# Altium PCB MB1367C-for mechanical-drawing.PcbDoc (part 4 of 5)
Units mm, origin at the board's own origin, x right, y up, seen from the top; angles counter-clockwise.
Board outline 70 x 82.5 mm, 4 copper layers (Top Layer, Signal Layer 1, Signal Layer 2, Bottom Layer), stack 1.614 mm thick; 191 components, 143 nets, 808 pads, 920 vias.
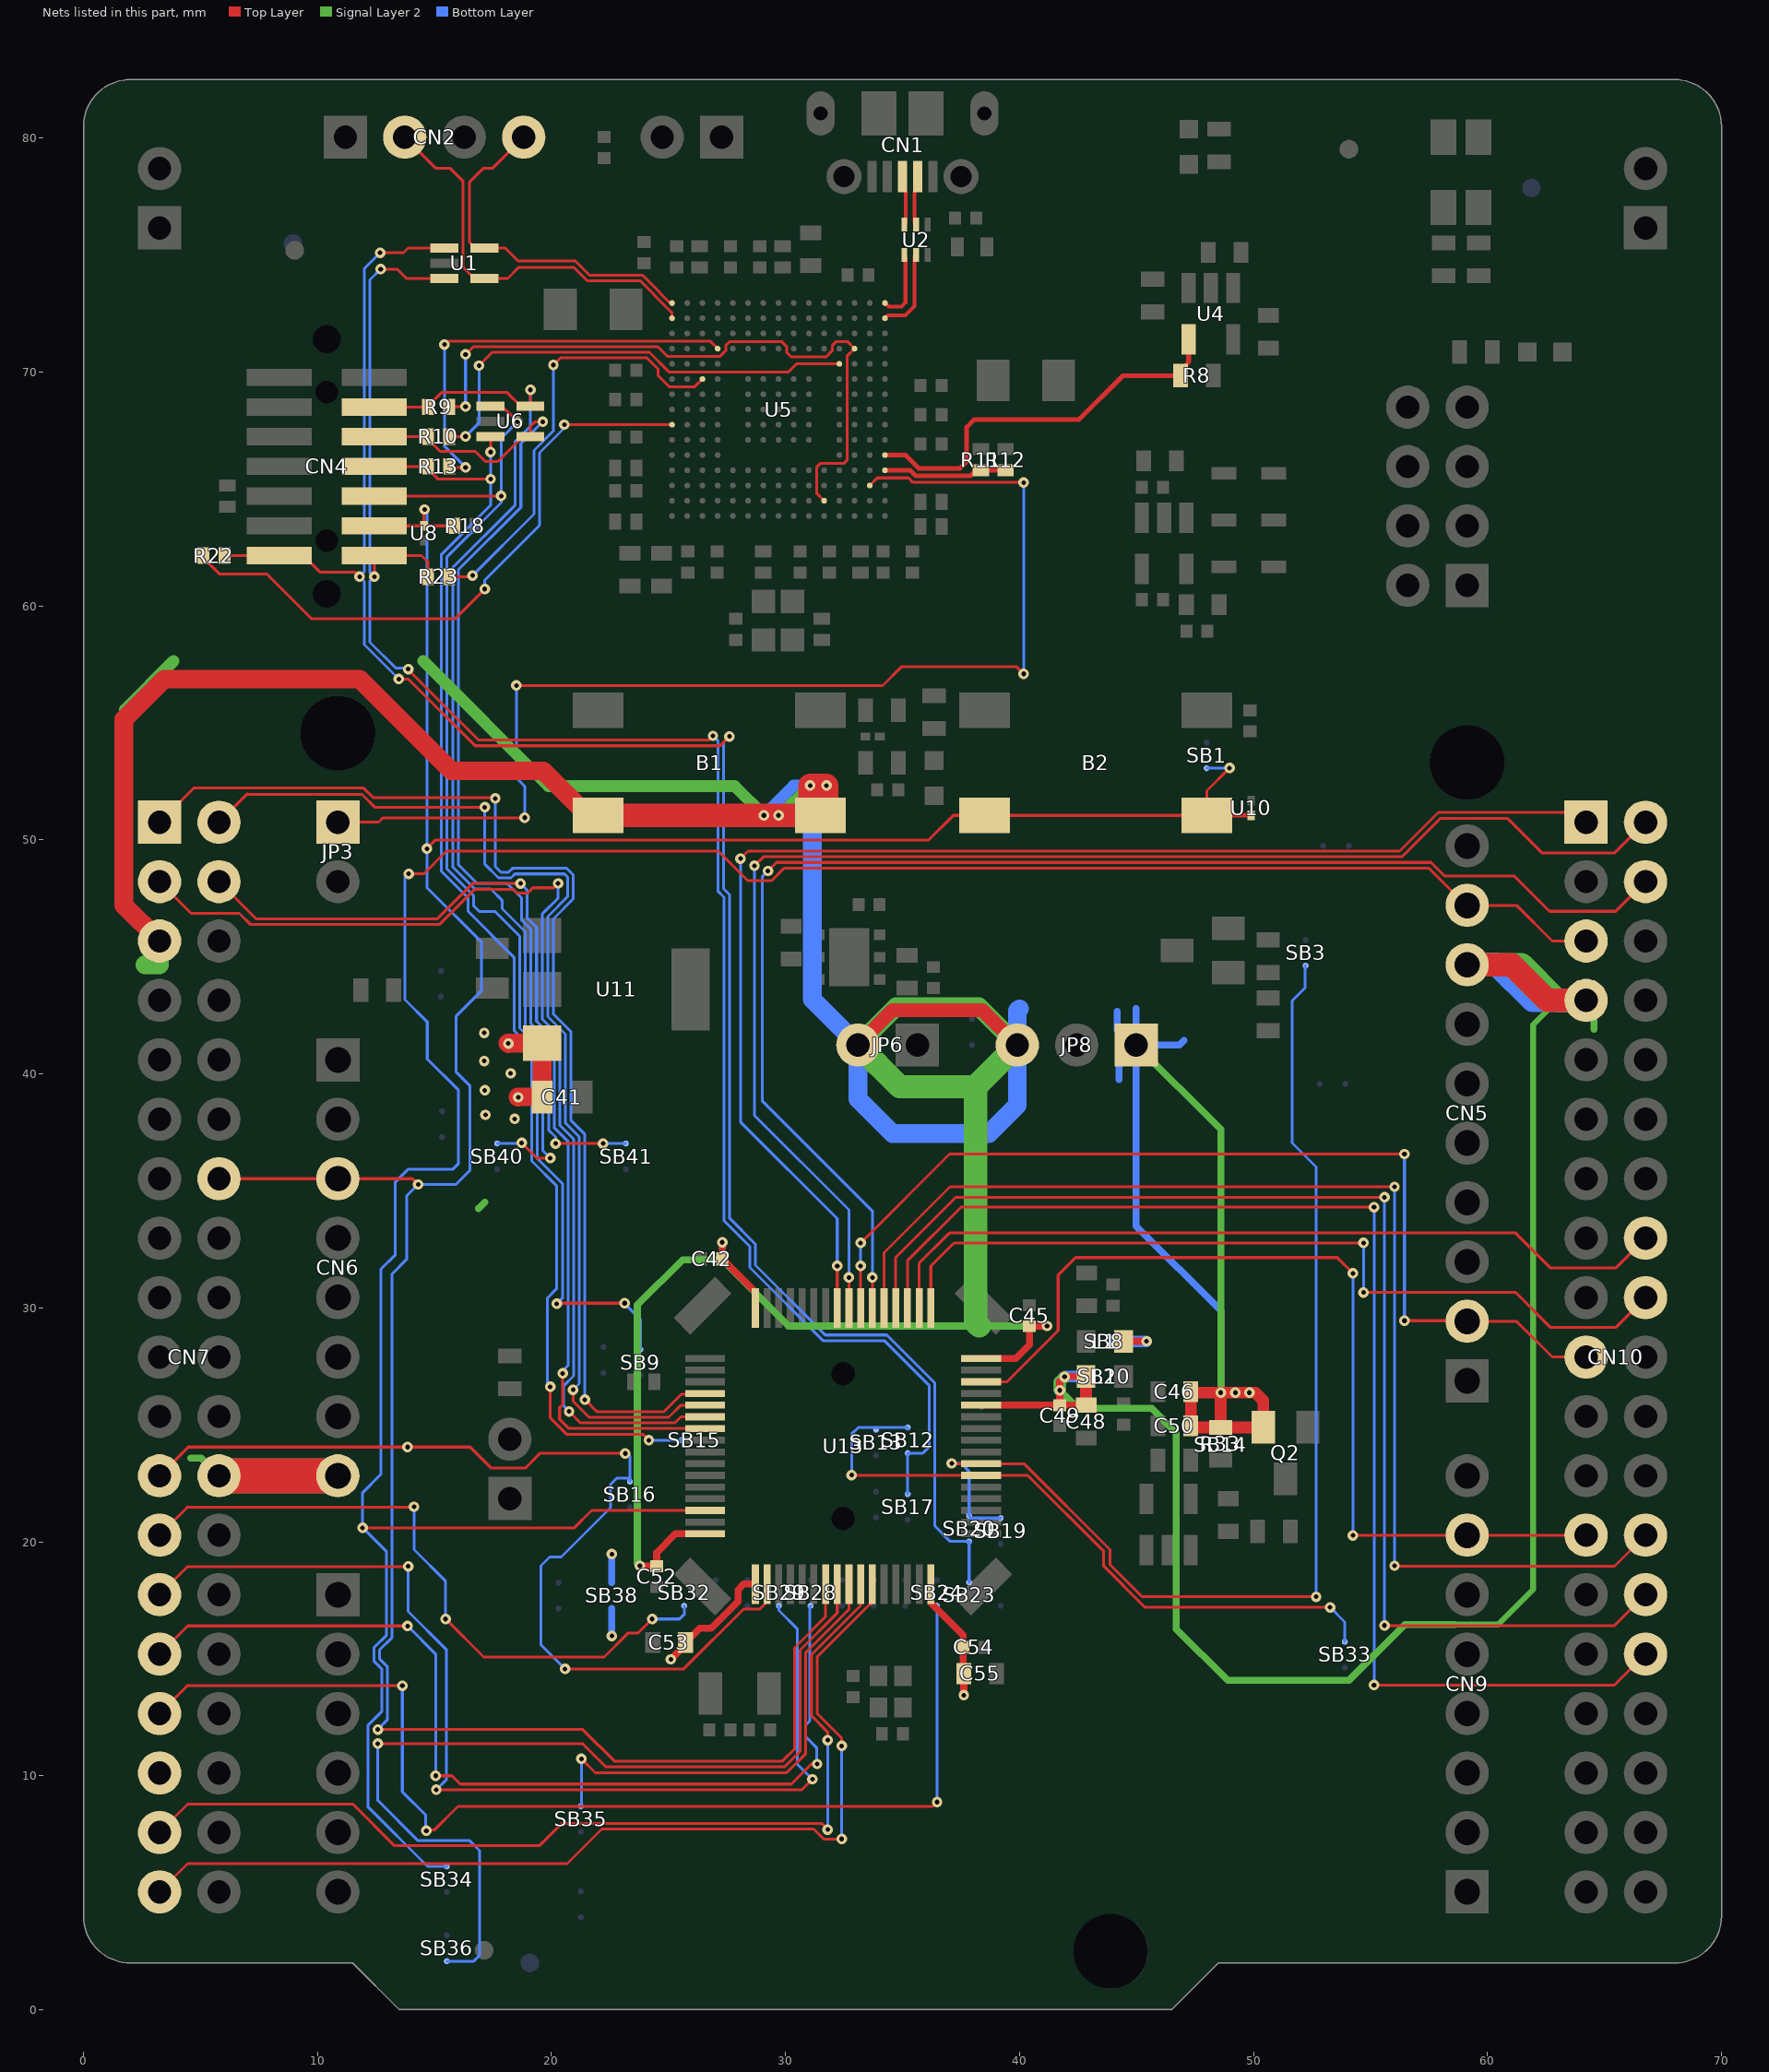
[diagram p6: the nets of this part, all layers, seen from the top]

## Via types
v1: diameter 0.45, hole 0.2, Top Layer to Bottom Layer, tented both sides, 920 vias

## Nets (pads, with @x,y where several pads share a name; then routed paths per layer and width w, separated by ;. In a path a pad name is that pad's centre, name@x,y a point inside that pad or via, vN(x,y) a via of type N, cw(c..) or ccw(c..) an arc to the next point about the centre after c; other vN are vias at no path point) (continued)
PB9: CN5.9 CN10.5 SB34.2 U13.62 | length 116.9
  Top Layer w0.12: v1(11.925,20.6) 20.975,20.6 21.715,21.34 U13.62@26.56,21.34 ; v1(13.895,48.55) 14.539,48.55 15.509,49.52 27.13,49.52 28.38,48.27 29.418,48.27 29.948,48.8 57.486,48.8 59.082,47.204 CN5.9@59.13,47.204 61.241,47.204 62.765,45.68 CN10.5@64.21,45.68
  Bottom Layer w0.12: v1(13.895,48.55) 13.736,48.391 13.736,43.175 14.69,42.221 14.69,40.637 16.025,39.302 16.025,36.17 15.775,35.92 13.866,35.92 13.325,35.379 13.325,32.268 12.71,31.653 12.71,22.885 11.925,22.1 v1(11.925,20.6) 12.95,19.575 12.95,16.014 12.405,15.469 12.405,14.908 12.74,14.573 12.74,12.74 12.15,12.15 12.15,8.675 14.7,6.125 SB34.2@15.525,6.125
PB10: CN9.7 CN10.25 U13.30 | length 40.9
  Top Layer w0.12: U13.30@38.36,26.84 39.465,26.84 41.65,29.025 41.65,31.4 42.4,32.15 53.575,32.15 v1(54.25,31.475) ; v1(54.25,20.275) 55.55,20.275 55.555,20.28 CN9.7@59.13,20.28 CN10.25@64.21,20.28
  Bottom Layer w0.12: v1(54.25,20.275) v1(54.25,31.475)
PB11: CN10.18 U13.33 | length 36
  Top Layer w0.12: U13.33@36.21,29.99 36.21,31.785 37.2,32.775 v1(54.7,32.775) ; v1(54.7,30.66) 61.2,30.66 62.7,29.16 65.47,29.16 CN10.18@66.75,30.44
  Bottom Layer w0.12: v1(54.7,30.66) v1(54.7,32.775)
PB12: CN10.16 U13.34 | length 34.6
  Top Layer w0.12: U13.34@35.71,29.99 35.71,31.91 37,33.2 61.2,33.2 62.7,31.7 65.47,31.7 CN10.16@66.75,32.98
PB13: CN10.30 U13.35 | length 55.5
  Top Layer w0.12: U13.35@35.21,29.99 35.21,32.01 37.5,34.3 v1(55.15,34.3) ; v1(55.15,13.875) 55.595,13.875 55.6,13.88 65.43,13.88 CN10.30@66.75,15.2
  Bottom Layer w0.12: v1(55.15,13.875) v1(55.15,34.3)
PB14: CN10.28 U13.36 | length 54.1
  Top Layer w0.12: U13.36@34.71,29.99 34.71,32.16 37.275,34.725 v1(55.6,34.725) ; v1(55.6,16.425) 55.605,16.42 65.43,16.42 CN10.28@66.75,17.74
  Bottom Layer w0.12: v1(55.6,16.425) v1(55.6,34.725)
PB15: CN10.26 U13.37 | length 52.8
  Top Layer w0.12: U13.37@34.21,29.99 34.21,32.36 37.025,35.175 v1(56.025,35.175) ; v1(56.025,18.975) 56.04,18.96 65.43,18.96 CN10.26@66.75,20.28
  Bottom Layer w0.12: v1(56.025,18.975) v1(56.025,35.175)
PC0: SB36.1 U13.8 | length 40.2
  Top Layer w0.12: v1(12.575,11.375) 21.325,11.375 22.315,10.385 29.967,10.385 30.625,11.043 30.625,15.372 32.21,16.957 U13.8@32.21,18.19
  Bottom Layer w0.12: v1(12.575,11.375) 12.575,8.95 14.3,7.225 16.5,7.225 16.925,6.8 16.925,2.325 16.675,2.075 SB36.1@15.525,2.075
PC1: SB35.1 U13.9 | length 20.2
  Top Layer w0.12: v1(21.275,10.725) 21.875,10.125 30.046,10.125 30.865,10.944 30.865,15.273 32.71,17.118 U13.9@32.71,18.19
  Bottom Layer w0.12: SB35.1@21.25,8.7 21.275,8.725 v1(21.275,10.725)
PC2: CN7.35 U13.10 | length 41.9
  Top Layer w0.12: CN7.35@3.25,7.58 4.455,8.785 11.515,8.785 13.295,7.005 19.48,7.005 20.44,7.965 31.535,7.965 v1(31.8,7.7) ; v1(31.8,11.525) 31.8,11.874 31.105,12.569 31.105,15.173 33.21,17.278 U13.10@33.21,18.19
  Bottom Layer w0.12: v1(31.8,7.7) v1(31.8,11.525)
PC3: CN7.37 U13.11 | length 42.8
  Top Layer w0.12: CN7.37@3.25,5.04 4.455,6.245 20.672,6.245 22.152,7.725 31.2,7.725 31.63,7.295 32.38,7.295 32.4,7.275 v1(32.4,7.3) ; v1(32.4,11.275) 32.4,11.613 31.345,12.668 31.345,15.074 33.431,17.16 33.435,17.16 33.54,17.265 33.54,17.269 33.586,17.315 33.615,17.315 33.71,17.41 U13.11@33.71,18.19
  Bottom Layer w0.12: v1(32.4,7.3) v1(32.4,11.275)
PC4: SB12.2 SB13.1 SB33.2 U13.22 | length 29.3
  Top Layer w0.12: v1(32.825,22.85) 32.835,22.84 40.353,22.84 43.595,19.598 43.595,18.962 45.357,17.2 v1(53.275,17.2)
  Bottom Layer w0.12: v1@32.825,22.825 v1(32.825,22.85) 32.825,24.6 33.115,24.89 SB12.2@35.22,24.89 SB12.2@35.22,24.805 ; v1(53.275,17.2) 53.9,16.575 SB33.2@53.9,15.725
PC5: SB3.2 SB19.1 SB20.2 U13.23 | length 50.1
  Top Layer w0.12: v1@37.075,23.35 37.085,23.34 40.193,23.34 43.87,19.663 43.87,19.026 45.246,17.65 v1(52.675,17.65)
  Bottom Layer w0.12: v1(37.1,23.35) 37.5,23.35 37.845,23.005 SB20.2@37.845,21.115 37.945,21.015 SB19.1@39.195,21.015 ; SB3.2@52.225,44.625 52.2,44.6 52.2,43.675 51.65,43.125 51.65,37.05 52.675,36.025 v1(52.675,17.65)
PC6: CN10.4 U13.38 | length 59.8
  Top Layer w0.12: v1(29.25,48.675) 29.615,49.04 57.585,49.04 58.175,48.45 61.15,48.45 62.65,46.95 65.48,46.95 CN10.4@66.75,48.22 ; U13.38@33.71,29.99 v1(33.71,31.3)
  Bottom Layer w0.12: v1(29.25,48.675) 29,48.425 29,38.85 33.71,34.14 v1(33.71,31.3)
PC7: CN5.2 CN10.19 U13.39 | length 43.1
  Top Layer w0.12: U13.39@33.21,29.99 v1(33.21,31.79) ; v1(33.21,32.775) 37.01,36.575 v1(56.45,36.575) ; v1(56.45,29.45) 59.104,29.45 CN5.2@59.13,29.424 61.241,29.424 62.765,27.9 CN10.19@64.21,27.9
  Bottom Layer w0.12: v1(33.21,31.79) v1(33.21,32.775) ; v1(56.45,29.45) v1(56.45,36.575)
PC8: CN10.2 U13.40 | length 60.7
  Top Layer w0.12: v1(28.673,48.9) 29.053,49.28 56.344,49.28 57.993,50.929 60.846,50.929 62.325,49.45 65.44,49.45 CN10.2@66.75,50.76 ; U13.40@32.71,29.99 v1(32.71,31.3)
  Bottom Layer w0.12: v1(28.673,48.9) 28.675,48.902 28.675,38.225 32.71,34.19 v1(32.71,31.3)
PC9: CN10.1 U13.41 | length 58
  Top Layer w0.12: v1(28.075,49.2) 28.395,49.52 56.245,49.52 57.9,51.175 63.795,51.175 CN10.1@64.21,50.76 ; U13.41@32.21,29.99 v1(32.21,31.79)
  Bottom Layer w0.12: v1(28.075,49.2) 28.075,37.95 32.21,33.815 v1(32.21,31.79)
PC10: CN7.1 U13.52 | length 50.7
  Top Layer w0.12: CN7.1@3.25,50.76 4.705,52.215 11.972,52.215 12.382,51.805 17.566,51.805 v1(17.596,51.775) ; v1(21.425,26.075) 21.94,25.56 24.8,25.56 25.55,26.31 26.56,26.31 U13.52@26.56,26.34
  Bottom Layer w0.12: v1(17.596,51.775) 17.596,48.86 17.833,48.622 18.169,48.622 18.334,48.787 20.649,48.787 20.93,48.507 20.93,47.478 20.08,46.628 20.08,42.551 20.835,41.796 20.835,38.001 21.425,37.411 v1(21.425,26.075)
PC11: CN7.2 U13.53 | length 48
  Top Layer w0.12: CN7.2@5.79,50.76 7.005,51.975 7.035,51.945 11.903,51.945 12.448,51.4 v1(17.15,51.4) ; v1(20.925,26.5) 20.925,26.002 21.607,25.32 25.005,25.32 25.525,25.84 U13.53@26.56,25.84
  Bottom Layer w0.12: v1(17.15,51.4) 17.15,48.966 17.734,48.382 18.268,48.382 18.433,48.547 20.55,48.547 20.69,48.407 20.69,47.578 19.84,46.728 19.84,42.451 20.595,41.696 20.595,37.901 21.185,37.311 21.185,26.76 v1(20.925,26.5)
PC12: CN7.3 U13.54 | length 48.5
  Top Layer w0.12: CN7.3@3.25,48.22 4.605,46.865 6.66,46.865 7.145,46.38 15.208,46.38 16.723,47.895 18.344,47.895 18.509,47.73 18.98,47.73 19.205,47.955 20.098,47.955 v1(20.285,48.142) ; v1(20.75,25.575) 21.245,25.08 25.265,25.08 25.525,25.34 U13.54@26.56,25.34
  Bottom Layer w0.12: v1(20.285,48.142) 20.275,48.15 20.275,47.502 19.6,46.827 19.6,42.352 20.355,41.597 20.355,37.802 20.945,37.212 20.945,27.093 20.52,26.668 20.52,25.805 v1(20.75,25.575)
PC13: CN7.23 SB16.2 U13.2 | length 43.7
  Top Layer w0.12: CN7.23@3.25,22.82 4.48,24.05 v1(13.85,24.05) 16.525,24.05 17.425,23.15 18.875,23.15 19.501,23.776 v1(23.151,23.776) ; v1(20.575,14.57) 25.65,14.57 28.205,17.125 28.9,17.125 29.21,17.435 U13.2@29.21,18.19
  Bottom Layer w0.12: v1(20.575,14.57) 19.55,15.595 19.55,18.975 19.925,19.35 20.417,19.35 22.525,21.458 22.525,22.45 22.8,22.725 23.35,22.725 ; v1(23.151,23.776) 23.249,23.776 23.35,23.675 23.35,22.725 ; SB16.2@23.35,22.575 23.35,22.725
PC14: CN7.25 SB32.1 | length 28.7
  Top Layer w0.12: CN7.25@3.25,20.28 4.455,21.485 14.11,21.485 v1(14.125,21.5) ; v1(15.475,16.7) 17.1,15.075 22.248,15.075 23.278,16.105 23.705,16.105 v1(24.3,16.7)
  Bottom Layer w0.12: v1(14.125,21.5) 14.125,19.664 15.475,18.314 v1(15.475,16.7) ; v1(24.3,16.7) 25.475,16.7 25.67,16.895 SB32.1@25.67,17.265
PC15: CN7.27 SB29.1 | length 45.8
  Top Layer w0.12: CN7.27@3.25,17.74 4.455,18.945 13.87,18.945 v1(13.875,18.95) ; v1(15.075,9.4) 15.08,9.405 30.705,9.405 v1(31.15,9.85)
  Bottom Layer w0.12: v1(13.875,18.95) 13.875,17.025 15.5,15.4 15.5,9.825 v1(15.075,9.4) ; SB29.1@29.72,17.265 29.72,17.065 30.5,16.285 30.5,10.5 v1(31.15,9.85)
PD2: CN7.4 U13.55 | length 44.4
  Top Layer w0.12: CN7.4@5.79,48.22 7.39,46.62 15.108,46.62 16.624,48.135 v1(18.677,48.135) ; v1(20.476,27.201) 20.476,25.874 20.345,25.743 20.345,25.234 20.739,24.84 U13.55@26.56,24.84
  Bottom Layer w0.12: v1(18.677,48.135) 18.965,47.847 18.965,46.666 19.36,46.271 19.36,42.252 20.115,41.497 20.115,37.702 20.705,37.112 20.705,27.53 20.476,27.301 v1(20.476,27.201)
PF0: CN7.29 SB28.1 | length 41.9
  Top Layer w0.12: CN7.29@3.25,15.2 4.455,16.405 13.845,16.405 v1(13.85,16.4) ; v1(15.05,10) 15.742,10 16.097,9.645 30.245,9.645 31.101,10.501 v1(31.352,10.501)
  Bottom Layer w0.12: v1(13.85,16.4) 15.05,15.2 v1(15.05,10) ; SB28.1@31.07,17.265 31.035,17.23 31.035,12.35 30.865,12.18 30.865,11.662 31.325,11.202 31.325,10.527 v1(31.352,10.501)
PF1: CN7.31 SB24.1 | length 48.3
  Top Layer w0.12: CN7.31@3.25,12.66 4.455,13.865 4.47,13.85 v1(13.625,13.85) ; v1(14.651,7.65) 14.675,7.675 14.989,7.675 15.999,8.685 36.285,8.685 v1(36.475,8.875)
  Bottom Layer w0.12: v1(13.625,13.85) 13.625,9.313 14.625,8.312 14.625,7.65 v1(14.651,7.65) ; SB24.1@36.47,17.265 36.425,17.22 36.475,17.17 v1(36.475,8.875)
STLK_SWCLK: CN2.2 U1.4 U5.A14 | length 17.3
  Top Layer w0.12: CN2.2@13.73,80.04 15.07,78.7 15.675,78.7 16.225,78.15 16.225,74.475 16.7,74 U1.4@17.125,74 18.125,74 18.605,74.48 20.95,74.48 21.53,73.9 23.795,73.9 24.375,73.32 24.375,73.294 25.024,72.645 25.03,72.645 25.15,72.525 U5.A14@25.15,72.3
STLK_SWDIO: CN2.4 U1.5 U5.A15 | length 15.4
  Top Layer w0.12: CN2.4@18.81,80.04 17.47,78.7 17.075,78.7 16.5,78.125 16.5,75.55 16.75,75.3 U1.5@17.125,75.3 18.025,75.3 18.575,74.75 21.019,74.75 21.629,74.14 23.894,74.14 24.615,73.419 24.615,73.399 25.064,72.95 U5.A15@25.15,72.95
STLK_VCP_RX: R23.1 U5.C10 | length 18.8
  Top Layer w0.12: R23.1@15.625,61.25 16.575,61.25 v1(16.627,61.302) ; v1(20.08,70.305) 20.075,70.305 20.375,70.605 24.081,70.605 24.555,70.13 24.555,69.845 25.025,69.375 26.125,69.375 U5.C10@26.45,69.7
  Bottom Layer w0.12: v1(16.627,61.302) 19.25,63.925 19.25,66.65 20.08,67.48 v1(20.08,70.305)
STLK_VCP_TX: R22.1 U5.A7 | length 26.8
  Top Layer w0.12: R22.1@5.125,62.15 5.125,62.05 5.8,61.375 7.825,61.375 9.75,59.45 15.875,59.45 v1(17.15,60.725) ; v1(20.55,67.75) U5.A7@25.15,67.75
  Bottom Layer w0.12: v1(17.15,60.725) 17.15,61.111 19.49,63.451 19.49,66.551 20.55,67.611 v1(20.55,67.75)
T_JTDI: CN4.10 SB9.1 U6.1 | length 53.5
  Top Layer w0.12: CN4.10@12.427,64.695 17.845,64.695 v1(17.85,64.7) ; U6.1@17.395,68.54 17.885,68.54 v1(18.55,67.875) ; v1(20.225,30.175) 20.25,30.2 v1(23.125,30.2)
  Bottom Layer w0.12: v1(18.55,67.875) 17.85,67.175 v1(17.85,64.7) 17.85,64.42 15.535,62.105 15.535,48.751 16.67,47.616 16.67,47.182 16.907,46.945 17.578,46.945 18.64,45.883 18.64,41.954 19.395,41.199 19.395,36.38 20.465,35.31 20.465,30.415 v1(20.225,30.175) ; v1(23.125,30.2) 23.1,30.2 23.795,29.505 SB9.1@23.795,28.215
T_NRST: B2.1 B2.2 CN4.12 CN6.3 CN7.14 R18.2 SB1.2 U8.1 U10.1 U13.7 | length 134.8
  Top Layer w0.12: CN7.14@5.79,35.52 CN6.3@10.87,35.52 14.055,35.52 v1(14.3,35.275) ; CN4.12@12.427,63.425 14.543,63.425 U8.1@14.545,63.427 ; v1(12.575,11.975) 21.336,11.975 22.686,10.625 29.867,10.625 30.385,11.143 30.385,15.471 31.71,16.796 U13.7@31.71,18.19 ; v1(14.575,64.125) 14.545,64.095 U8.1@14.545,63.427 ; v1(14.675,49.625) 15.05,50 36.125,50 37.175,51.05 B2.2@38.505,51.05 B2.1@48.005,51.05 ; R18.2@15.85,63.425 14.547,63.425 U8.1@14.545,63.427 ; B2.1@48.008,51.052 B2.1@48.005,51.05 ; v1(48.975,53.075) 48.005,52.105 B2.1@48.005,51.05
  Top Layer w0.2: B2.1@48.008,51.052 U10.1@49.895,51.052
  Bottom Layer w0.12: v1(12.575,11.975) 12.98,12.38 12.98,14.672 12.645,15.007 12.645,15.37 13.19,15.915 13.19,31.454 13.805,32.069 13.805,34.78 v1(14.3,35.275) 15.913,35.275 16.505,35.867 16.505,39.501 15.93,40.076 15.93,42.475 17.01,43.555 17.01,45.631 14.675,47.966 v1(14.675,49.625) 14.675,64.025 v1(14.575,64.125) ; SB1.2@47.995,53.065 48.965,53.065 v1(48.975,53.075)
T_NRSTa: JP3.1 U5.P3 | length 51
  Top Layer w0.12: JP3.1@10.87,50.76 12.61,50.76 12.8,50.95 v1(18.85,50.95) ; v1(18.5,56.6) 34.15,56.6 34.95,57.4 39.875,57.4 v1(40.175,57.1) ; U5.P3@33.6,65.15 33.925,65.475 35.251,65.475 35.446,65.28 40.145,65.28 40.15,65.275 v1(40.175,65.275)
  Bottom Layer w0.12: v1(18.5,56.6) 18.5,52.65 18.85,52.3 v1(18.85,50.95) ; v1(40.175,57.1) v1(40.175,65.275)
T_PWR_EN: R8.1 U4.4 U5.R5 | length 17.1
  Top Layer w0.2: U5.R5@34.25,66.45 35.125,66.45 35.695,65.88 37.455,65.88 37.745,66.17 37.745,67.645 38.075,67.975 42.55,67.975 44.42,69.845 R8.1@46.885,69.845 46.885,70.085 47.225,70.425 U4.4@47.225,71.395
T_PWR_EXT: R11.2 R12.2 U5.R4 | length 5.3
  Top Layer w0.2: U5.R4@34.25,65.8 35.322,65.8 35.562,65.56 37.91,65.56 38.15,65.8 R11.2@38.35,65.8 R12.2@39.4,65.8
T_SWCLK: CN4.6 R10.2 SB41.1 U6.4 | length 46.5
  Top Layer w0.12: CN4.6@12.427,67.235 14.715,67.235 R10.2@14.72,67.24 14.72,67.13 15.25,66.6 16.75,66.6 17.175,66.175 17.7,66.175 18.765,67.24 U6.4@19.095,67.24 19.095,67.67 19.3,67.875 v1(19.625,67.875) ; v1(20.175,37.025) v1(22.2,37.025)
  Bottom Layer w0.12: v1(19.625,67.875) 18.69,66.94 18.69,64.215 16.015,61.54 16.015,48.95 16.823,48.142 18.097,48.142 18.725,47.514 18.725,46.567 19.12,46.172 19.12,42.153 19.875,41.398 19.875,37.603 20.175,37.303 v1(20.175,37.025) ; v1(22.2,37.025) SB41.1@23.175,37.025
T_SWCLKa: R10.1 U5.M11 | length 20.1
  Top Layer w0.12: R10.1@15.62,67.24 16.315,67.24 v1(16.325,67.25) ; v1(16.9,70.275) 17.47,70.845 24.18,70.845 25.02,70.005 30.13,70.005 30.475,70.35 U5.M11@32.3,70.35
  Bottom Layer w0.12: v1(16.325,67.25) 16.9,67.825 v1(16.9,70.275)
T_SWDIO: CN4.4 R9.2 SB40.1 U6.5 | length 47
  Top Layer w0.12: CN4.4@12.427,68.505 R9.2@14.71,68.505 ; R9.2@14.75,68.525 14.75,68.575 15.3,69.125 18.1,69.125 18.685,68.54 U6.5@19.095,68.54 19.095,69.345 19.1,69.34 v1(19.1,69.24) ; v1(18.725,37.05) 19.375,36.4 v1(19.95,36.4)
  Bottom Layer w0.12: SB40.1@17.675,37.025 18.7,37.025 v1(18.725,37.05) ; v1(19.1,69.24) 19.1,67.689 18.45,67.039 18.45,64.314 15.775,61.639 15.775,48.851 16.723,47.902 17.4,47.902 17.9,47.403 17.895,47.398 17.895,47.057 18.88,46.072 18.88,42.054 19.635,41.299 19.635,36.715 v1(19.95,36.4)
T_SWDIOa: R9.1 U5.L2 U5.N12 | length 29.1
  Top Layer w0.12: R9.1@15.62,68.515 16.315,68.515 v1(16.325,68.525) ; v1(16.325,70.75) 16.66,71.085 24.54,71.085 24.95,70.675 27.206,70.675 27.445,70.914 27.445,71.126 27.624,71.305 29.826,71.305 30.045,71.086 30.045,70.844 30.239,70.65 31.731,70.65 31.995,70.914 31.995,71.126 32.174,71.305 32.645,71.305 U5.N12@32.95,71 32.625,70.675 32.625,66.225 32.505,66.105 31.505,66.105 31.325,65.925 31.325,64.825 U5.L2@31.65,64.5
  Bottom Layer w0.12: v1(16.325,68.525) v1(16.325,70.75)
T_SWO: CN4.8 R13.2 SB15.2 U6.3 | length 56.7
  Top Layer w0.12: CN4.8@12.427,65.965 R13.2@14.72,65.965 14.72,65.855 15.14,65.435 17.39,65.435 v1(17.4,65.425) ; U6.3@17.015,67.24 U6.3@17.395,67.24 v1(17.395,66.58) ; v1(19.95,26.625) 19.95,25.289 20.639,24.6 23.9,24.6 v1(24.16,24.34)
  Bottom Layer w0.12: v1@17.395,66.575 v1(17.395,66.58) ; v1@17.4,66.575 v1(17.4,65.425) 17.4,64.309 15.295,62.204 15.295,48.652 16.43,47.517 16.43,46.947 18.4,44.977 18.4,41.855 19.155,41.1 19.155,36.281 20.225,35.211 20.225,30.825 19.82,30.42 19.82,26.755 v1(19.95,26.625) ; v1(24.16,24.34) SB15.2@25.545,24.34
T_SWOa: R13.1 U5.D12 | length 18.3
  Top Layer w0.12: v1(15.425,71.175) 15.575,71.325 26.775,71.325 U5.D12@27.1,71 ; R13.1@15.62,65.965 15.66,65.925 v1(16.325,65.925) v1@16.425,65.925
  Bottom Layer w0.12: v1(15.425,71.175) 15.42,71.17 15.42,66.83 v1(16.325,65.925)
T_VCP_RX: CN4.13 R22.2 SB20.1 SB23.1 U1.1 | length 86.4
  Top Layer w0.12: R22.2@6.025,62.15 8.358,62.15 8.37,62.138 8.375,62.143 9.407,62.143 10.1,61.45 11.6,61.45 v1(11.8,61.25) ; v1(12.675,75.1) 13.675,75.1 13.875,75.3 U1.1@15.425,75.3 ; v1(13.475,56.875) 13.886,56.875 16.736,54.025 27.2,54.025 v1(27.6,54.425)
  Bottom Layer w0.12: v1(12.675,75.1) 12,74.425 12,61.45 v1(11.8,61.25) 12,61.05 12,58.35 v1(13.475,56.875) ; v1(27.6,54.425) 27.35,54.175 27.35,47.914 27.615,47.649 27.615,33.824 28.715,32.724 28.715,31.824 31.699,28.84 34.324,28.84 36.375,26.789 36.375,20.675 37.035,20.015 SB20.1@37.845,20.015 SB23.1@37.845,18.265
T_VCP_TX: CN4.14 R23.2 SB12.1 SB17.1 U1.3 | length 78.3
  Top Layer w0.12: v1(12.425,61.25) v1(12.425,61.25) CN4.14@12.427,62.155 14.445,62.155 14.725,61.875 R23.2@14.725,61.25 ; v1(12.7,74.4) 13.4,74.4 13.8,74 U1.3@15.425,74 ; v1(13.875,57.3) 13.95,57.375 13.95,57.2 16.885,54.265 26.715,54.265 v1(26.9,54.45)
  Bottom Layer w0.12: v1(12.7,74.4) 12.24,73.94 12.24,61.435 v1(12.425,61.25) 12.24,61.065 12.24,58.449 13.345,57.345 13.83,57.345 v1(13.875,57.3) ; v1(26.9,54.45) 27.11,54.24 27.11,47.815 27.375,47.55 27.375,33.725 28.475,32.625 28.475,31.725 31.6,28.6 34.225,28.6 36.135,26.69 36.135,24.055 35.87,23.79 SB12.1@35.22,23.79 SB17.1@35.22,22.04
USB_DEV_HS_CN_N: CN1.2 U2.5 | length 2.1
  Top Layer w0.16: U2.5@35.575,76.3 35.518,76.357 35.518,77.693 35.65,77.825 CN1.2@35.65,78.35
USB_DEV_HS_CN_P: CN1.3 U2.6 | length 2.1
  Top Layer w0.16: CN1.3@35,78.35 35,77.825 35.132,77.693 35.132,76.357 U2.6@35.075,76.3
USB_DEV_HS_N: U2.2 U5.R14 | length 3.7
  Top Layer w0.16: U5.R14@34.25,72.3 34.364,72.414 35.114,72.414 35.518,72.818 35.518,74.943 U2.2@35.575,75
USB_DEV_HS_P: U2.1 U5.R15 | length 3.1
  Top Layer w0.16: U5.R15@34.25,72.95 34.4,72.8 34.954,72.8 35.125,72.971 35.125,74.95 U2.1@35.075,75
VBAT: C53.2 CN7.33 SB38.2 U13.1 | length 6.5
  Top Layer w0.3: v1(25.1,14.975) 25.725,15.6 C53.2@25.725,15.7 26.33,16.305 26.825,16.305 27.967,17.448 27.967,17.942 28.215,18.19 U13.1@28.71,18.19
  Bottom Layer w0.3: v1(22.575,15.975) SB38.2@22.575,17.15
VDD: B1.1 B1.2 C42.2 C45.2 C52.2 C54.2 C55.2 CN7.5 JP6.2 JP8.3 L1.1 SB8.1 SB38.1 U13.16 U13.32 U13.48 U13.64 | length 201.2
  Top Layer w0.3: v1(23.775,18.975) 23.785,18.965 C52.2@24.495,18.965 24.495,19.545 25.29,20.34 U13.64@26.56,20.34 ; v1(27.3,32.8) 27.295,32.795 C42.2@27.295,32.09 27.31,32.09 28.71,30.69 U13.48@28.71,29.99 ; U13.16@36.21,18.19 36.21,17.39 37.595,16.005 C54.2@37.595,15.49 37.595,14.39 C55.2@37.62,14.365 v1(37.62,13.445) ; U13.32@38.36,27.84 39.84,27.84 40.42,28.42 C45.2@40.42,29.215 41.185,29.215 v1(41.175,29.225) ; L1.1@44.445,28.565 44.455,28.575 v1(45.425,28.575)
  Top Layer w0.6: JP6.2@33.095,41.235 33.095,41.252 34.568,42.725 38.415,42.725 JP8.3@39.905,41.235
  Top Layer w0.8: CN7.5@3.25,45.68 1.725,47.205 1.725,55.15 3.45,56.875 11.8,56.875 15.725,52.95 19.65,52.95 B1.2@21.55,51.05
  Top Layer w1: B1.2@21.55,51.05 B1.2@21.995,51.05 v1(29.7,51.05) B1.1@31.495,51.05 ; B1.1@31.495,51.05 31.75,51.305 v1(31.75,52.325) v1(31.05,52.325) 31.05,51.495 B1.1@31.495,51.05
  Signal Layer 2 w0.3: v1(23.775,18.975) 23.665,19.085 23.665,30.115 25.6,32.05 27.3,32.05 ; v1(27.3,32.8) 27.3,32.05 ; v1(41.175,29.225) 38.275,29.225 30.125,29.225 27.3,32.05
  Signal Layer 2 w0.5: CN7.5@3.25,45.68 1.77,47.16 1.77,55.57 3.85,57.65 ; 14.515,57.65 19.865,52.3 27.825,52.3 v1(29.075,51.05) 29.775,51.05 v1(31.05,52.325) v1(31.75,52.325)
  Signal Layer 2 w0.8: 2.618,44.665 3.25,44.665 CN7.5@3.25,45.68 ; JP6.2@33.095,41.235 34.735,42.875 38.265,42.875 JP8.3@39.905,41.235
  Signal Layer 2 w1: JP6.2@33.095,41.235 34.88,39.45 38.12,39.45 ; 38.275,29.225 38.12,29.38 38.12,39.45 ; JP8.3@39.905,41.235 38.12,39.45
  Bottom Layer w0.3: SB38.1@22.575,18.25 v1(22.575,19.475) ; v1(37.62,13.445) v1@37.625,13.45 ; v1@45.415,28.565 v1(45.425,28.575)
  Bottom Layer w0.5: v1(29.075,51.05) v1@29.125,51.1 ; v1@29.1,51.1 v1@29.125,51.1 ; SB8.1@44.145,28.565 v1@45.415,28.565 ; v1@29.125,51.1 31.075,51.1 31.15,51.175 31.75,51.775 v1(31.75,52.325) v1(31.05,52.325) 30.35,52.325 v1@29.125,51.1
  Bottom Layer w0.8: v1(31.05,52.325) 31.15,52.225 31.15,51.175 31.15,43.18 JP6.2@33.095,41.235 33.095,38.93 34.575,37.45 38.7,37.45 39.905,38.655 JP8.3@39.905,41.235 39.905,42.69 40,42.785
VIN: C41.2 CN6.8 CN7.24 U11.3 | length 16.9
  Top Layer w0.8: v1(18.15,41.3) 18.135,41.315 U11.3@19.595,41.315 C41.2@19.595,39.015 18.56,39.015 v1(18.575,39)
  Top Layer w1.5: CN7.24@5.79,22.82 CN6.8@10.87,22.82
  Signal Layer 2 w0.3: 4.575,23.575 5.035,23.575 CN7.24@5.79,22.82 ; 16.88,34.248 17.15,34.518
  Signal Layer 2 w1.5: CN7.24@5.79,22.82 CN6.8@10.87,22.82
  other v1: 18.425,38.075 17.175,38.25 17.15,39.3 18.25,40.025 17.125,40.55 17.125,41.75
VREF: C46.2 C50.2 JP8.1 Q2.2 R33.2 SB14.1 | length 54.7
  Top Layer w0.5: R33.2@48.595,24.89 47.395,24.89 C50.2@47.32,24.965 C46.2@47.32,26.415 47.36,26.375 v1(48.6,26.375) ; R33.2@48.595,24.89 Q2.2@50.42,24.89 50.42,26.03 50.075,26.375 v1(49.825,26.375) v1(49.225,26.375) v1(48.6,26.375) ; R33.2@48.595,24.89 48.595,26.37 v1(48.6,26.375)
  Signal Layer 2 w0.3: JP8.1@44.985,41.235 48.6,37.62 v1(48.6,26.375) v1(49.225,26.375) v1(49.825,26.375)
  Bottom Layer w0.3: 44.175,42.675 44.175,41.875 44.815,41.235 JP8.1@44.985,41.235 ; 44.25,39.75 44.25,40.5 JP8.1@44.985,41.235 ; 44.975,42.785 44.985,42.775 JP8.1@44.985,41.235 ; 47.025,41.425 46.835,41.235 JP8.1@44.985,41.235 ; SB14.1@48.595,24.69 48.6,24.695 v1(48.6,26.375) ; v1(49.825,26.375) v1(49.225,26.375) v1(48.6,26.375) ; JP8.1@44.985,41.235 44.985,33.49 48.6,29.875 v1(48.6,26.375)
VREFP: C48.1 C49.1 CN5.8 CN10.7 L2.2 SB10.2 U13.28 | length 86.2
  Top Layer w0.3: U13.28@38.36,25.84 C49.1@41.72,25.84 ; C48.1@42.845,25.84 C49.1@41.72,25.84 ; L2.2@42.845,27.065 41.94,27.065 v1(41.925,27.05) 41.72,26.845 v1(41.72,26.475) C49.1@41.72,25.84
  Top Layer w0.5: C48.1@42.845,25.84 L2.2@42.845,27.065
  Top Layer w1: CN5.8@59.13,44.664 61.036,44.664 62.56,43.14 CN10.7@64.21,43.14
  Signal Layer 2 w0.25: 58.597,16.47 60.455,16.47 61.95,17.965 61.95,42.105 62.985,43.14
  Signal Layer 2 w0.3: v1(41.72,26.475) 42.495,25.7 45.65,25.7 46.7,24.65 46.7,16.275 48.9,14.075 54.075,14.075 56.47,16.47 58.597,16.47 ; CN10.7@64.21,43.14 64.55,42.8 64.55,41.9
  Signal Layer 2 w0.5: v1(41.72,26.475) 41.72,26.845 v1(41.925,27.05)
  Signal Layer 2 w1: CN5.8@59.13,44.664 61.461,44.664 62.985,43.14 CN10.7@64.21,43.14
  Bottom Layer w0.3: v1(41.925,27.05) v1@41.94,27.065
  Bottom Layer w0.5: v1(41.72,26.475) 41.72,26.845 v1(41.925,27.05) ; v1@41.94,27.065 42.845,27.065
  Bottom Layer w1: CN5.8@59.13,44.664 60.411,44.664 61.935,43.14 CN10.7@64.21,43.14
pads on no net: CN1.4 CN4.0 CN4.1 CN4.2 CN4.9 CN7.9 CN7.10 CN7.11 CN7.26 CN10.10 CN10.36 CN10.38 MP1.1 MP2.1 MP3.1 MP4.1 MP5.1 MP6.1 U2.4 U5.A1 U5.A2 U5.A3 U5.A4 U5.A5 U5.A6 U5.A8 U5.A9 U5.A10 U5.A11 U5.A12 U5.A13 U5.B1 U5.B2 U5.B3 U5.B4 U5.B5 U5.B6 U5.B7 U5.B8 U5.B9 U5.B10 U5.B11 U5.B12 U5.B13 U5.B14 U5.B15 U5.C2 U5.C3 U5.C4 U5.C11 U5.C12 U5.C13 U5.C14 U5.C15 U5.D1 U5.D2 U5.D3 U5.D4 U5.D10 U5.D11 U5.D13 U5.D14 U5.E1 U5.E2 U5.E3 U5.E4 U5.E12 U5.E13 U5.E14 U5.E15 U5.F1 U5.F4 U5.F14 U5.G4 U5.G14 U5.G15 U5.H1 U5.H2 U5.H3 U5.H4 U5.H14 U5.H15 U5.J2 U5.J3 U5.J4 U5.K1 U5.K2 U5.K3 U5.K12 U5.K14 U5.K15 U5.L1 U5.L3 U5.L12 U5.L13 U5.L14 U5.L15 U5.M2 U5.M3 U5.M4 U5.M5 U5.M6 U5.M7 U5.M12 U5.M13 U5.M14 U5.M15 U5.N2 U5.N4 U5.N5 U5.N6 U5.N7 U5.N11 U5.N13 U5.N14 U5.N15 U5.P2 U5.P4 U5.P5 U5.P6 U5.P7 U5.P8 U5.P9 U5.P10 U5.P11 U5.P12 U5.P13 U5.P14 U5.P15 U5.R2 U5.R3 U5.R6 U5.R7 U5.R8 U5.R9 U5.R10 U5.R11 U5.R12 U5.R13 U12.3 U12.5 U13.0 U14.1 U14.2

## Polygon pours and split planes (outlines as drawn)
GND on Top Layer "GND_L01_P086" (solid, remove dead copper, pour order 86): 39.725,82.2 39.725,73.05 38.95,72.275 37.1,72.275 37.1,69.35 38.174,68.276 42.476,68.276 43.675,69.475 49.95,69.475 50.65,70.175 50.65,71.925 50,72.575 48.725,72.575 48.5,72.8 48.5,76.5 49.5,77.5 49.9,77.5 49.9,82.2
GND on Top Layer "GND_L01_P084" (solid, remove dead copper, pour order 84): 13.3,39.675 13.35,39.675 14.025,39 16.075,39 16.4,38.675 16.4,37.8 16.875,37.325 20.625,37.325 20.825,37.525 20.824,37.526 20.824,38.001 24.976,38.001 26.875,39.9 28.4,39.9 28.4,28.825 29.425,27.8 39.5,27.8 39.5,23.525 44.175,18.85 49.625,18.85 49.625,13.625 48.2,12.2 44.1,12.2 43.55,11.65 43.55,8.625 44.2,7.975 69.65,7.975 69.7,7.925 69.7,3.4 68.525,2.225 48.3,2.225 46.275,0.2 13.675,0.2 9.95,3.925 9.95,39.65
GND on Top Layer "GND_L01_P082" (solid, remove dead copper, pour order 82): 33.425,75.125 22.475,75.125 21.875,74.525 21.875,71.775 23,70.65 23,61.95 23.2,61.75 36,61.75 36.375,62.125 36.375,71.9 36.675,72.2 37.85,72.2 38.7,71.35 38.7,66.525 39.35,65.875 44.5,65.875 45.475,66.85 48.725,66.85 49.125,66.45 49.125,59.4 49.9,58.625 60.85,58.625 61.225,59 61.225,64.425 61.375,64.575 61.375,71.425 62.25,72.3 62.25,73.5 61.775,73.975 54.75,73.975 51.225,77.5 49.775,77.5 49.775,82.3 49.75,82.325 49.825,82.4 68.625,82.4 69.85,81.175 69.85,14.5 63.8,14.5 61.5,12.2 48.2,12.2 47,13.4 47,26.775 46.45,27.325 29.075,27.325 27.85,28.55 27.85,47.025 27.05,47.825 19.125,47.825 16.15,44.85 16.15,44.75 14.35,44.75 13.575,43.975 13.575,2.375 13.55,2.35 1.5,2.35 0.2,3.65 0.2,81.1 1.3,82.2 32.325,82.2 33.4,81.125
AGND on Top Layer "AGND_L01_P064" (solid, remove dead copper, pour order 64): 44.35,11.75 44,11.4 44,8.8 44.425,8.375 68.475,8.375 68.925,8.825 68.925,13.925 68.625,14.225 65.65,14.225 63.175,11.75
5V on Top Layer "5V_L01_P028" (solid, remove dead copper, pour order 28): 59.775,69.638 58.463,69.638 56.575,67.75 54.25,67.75 53.875,67.375 45.3,67.375 44.175,66.25 39.175,66.25 39.025,66.4 39.025,67.625 39.175,67.775 42.8,67.775 44.025,69 50.175,69 53.075,71.9 59.525,71.9 59.775,71.65
GND on Top Layer "GND_L01_P006" (solid, remove dead copper, pour order 6): 20.625,45.025 20.35,44.75 16.15,44.75 15.875,45.025 15.875,48.2 16.275,48.6 20.275,48.6 20.625,48.25
5V_VIN on Top Layer "5V_VIN_L01_P004" (solid, remove dead copper, pour order 4): 15.775,42.375 15.525,42.125 14.075,42.125 14,42.2 14,43.735 14.765,44.5 16.3,44.5 20.4,44.5 21,45.1 21,46.925 21.425,47.35 26.8,47.35 27.3,46.85 27.3,40.7 26.725,40.125 21.7,40.125 21.225,40.6 21.225,41.825 20.675,42.375
VIN on Top Layer "VIN_L01_P008" (solid, remove dead copper, pour order 8): 20.5,42.125 20.625,42 20.625,38.025 20.35,37.75 17.1,37.75 16.75,38.1 16.75,41.85 17.025,42.125
GND on Top Layer "GND_L01_P010" (solid, remove dead copper, pour order 10): 20.975,39.9 20.8,39.725 20.8,38.025 21.075,37.75 26.95,37.75 27.275,38.075 27.275,39.5 26.875,39.9
5V_USB_CHGR on Top Layer "5V_USB_CHGR_L01_P032" (solid, remove dead copper, pour order 32): 54.392,65.417 56.592,65.417 58.3,67.125 60.65,67.125 60.9,67.375 60.9,69.25 60.725,69.425 58.775,69.425 56.725,67.375 54.575,67.375 54.225,67.025 49.875,67.025 49.5,66.65 49.5,65 49.7,64.8 53.775,64.8
E5V on Top Layer "E5V_L01_P034" (solid, remove dead copper, pour order 34): 49.775,64.525 49.5,64.25 49.5,63.05 49.75,62.8 56.375,62.8 58.325,64.75 60.55,64.75 60.875,65.075 60.875,66.775 60.725,66.925 58.7,66.925 56.825,65.05 54.425,65.05 53.9,64.525
5V_VIN on Top Layer "5V_VIN_L01_P036" (solid, remove dead copper, pour order 36): 49.775,62.525 49.525,62.275 49.525,59.575 50.05,59.05 60.525,59.05 60.875,59.4 60.875,64.175 60.575,64.475 58.475,64.475 56.525,62.525
AGND on Top Layer "AGND_L01_P066" (solid, remove dead copper, pour order 66): 46.5,23.025 46.25,23.275 46.25,24.875 46.25,26.875 46.025,27.1 45.275,27.1 45.125,26.95 45.125,25.575 44.9,25.35 44.095,25.35 43.97,25.225 41.05,25.225 40.925,25.35 40.82,25.35 40.75,25.28 40.75,23.375 43.625,20.5 46,20.5 46.5,21
5V_USB_STLK on Top Layer "5V_USB_STLK_L01_P078" (solid, remove dead copper, pour order 78): 49.5,77.075 49.1,76.675 49.1,74.95 48.825,74.675 48.825,72.9 48.85,72.925 51.775,72.925 52.45,72.25 61.65,72.25 61.85,72.45 61.85,73.325 61.575,73.6 54.575,73.6 51.1,77.075
GND on Top Layer "GND_L01_P002" (solid, remove dead copper, pour order 2): 31.675,77.625 33.25,76.05 33.25,71.275 34.15,70.375 38.15,70.375 40,72.225 40,82.5 30.65,82.5 30.65,78.675 31.675,77.65
GND on Bottom Layer "GND_L04_P110" (solid, remove dead copper, pour order 110): 52.835,57.81 52.82,57.825 50.075,57.825 48.475,59.425 46.65,59.425 46.65,45.35 47.9,44.1 50.175,44.1 51.425,42.85 54.025,42.85 54.025,56.701 52.876,57.851
GND on Bottom Layer "GND_L04_P108" (solid, remove dead copper, pour order 108): 10.725,82.3 10.725,63.3 14.4,59.625 21.8,59.625 24.925,62.75 24.925,81.925 24.55,82.3
GND on Bottom Layer "GND_L04_P106" (solid, remove dead copper, pour order 106): 18.325,58.725 18.325,55.4 21.725,52 27.5,52 28.925,53.425 33.425,53.425 33.9,53.9 33.9,57.975 33.15,58.725
GND on Bottom Layer "GND_L04_P104" (solid, remove dead copper, pour order 104): 1.15,57.85 5.65,62.35 5.65,65.025 4.525,66.15 4.525,69.275 4.95,69.7 9.375,69.7 10.2,68.875 10.2,60.65 12.4,58.45 12.4,32.6 11.125,31.325 0.825,31.325 0.275,30.775 0.275,3.525 1.525,2.275 11.375,2.275 13.425,0.225 46.475,0.225 48.525,2.275 68.525,2.275 69.8,3.55 69.8,81.05 68.625,82.225 12.054,82.225 11.55,81.721 11.55,75.65 13.8,73.4 13.8,62.25 19.45,56.6 33.85,56.6 35.8,58.55 35.8,63.65 36.4,64.25 38.65,64.25 39.35,63.55 39.35,44.675 39.925,44.1 47.9,44.1 48.925,45.125 48.925,69.85 49.875,70.8 57.475,70.8 57.75,71.075 57.725,71.1 57.725,72.55 55.95,74.325 49.075,74.325 48.5,74.9 48.5,77.5 48.875,77.875 60.425,77.875 64.5,73.8 64.5,58.6 63.751,57.851 52.876,57.851 51.775,56.75 51.775,24.85 50.975,24.05 50.875,24.15 48.525,24.15 47.675,23.3 47.675,9.175 46.55,8.05 42.45,8.05 41.325,9.175 41.325,20.325 40.425,21.225 40.425,22.975 39.775,23.625 36.85,23.625 36.05,24.425 36.05,26.025 36.075,26.025 37,26.95 40.825,26.95 41.575,27.7 41.575,34.45 40.725,35.3 32.775,35.3 28.2,39.875 20.85,39.875 20.25,39.275 20.25,37.75 19.725,37.225 16.425,37.225 15.85,37.8 15.85,41.95 16.675,42.775 19.225,42.775 19.95,43.5 19.95,46.35 21.5,47.9 27.125,47.9 27.925,48.7 27.925,57.375 27.45,57.85 18.775,57.85 13.8,62.825 13.8,74.25 12.225,75.825 12.225,82.125 12,82.35 1.5,82.35 0.325,81.175 0.325,57.975 0.45,57.85
3V3 on Bottom Layer "3V3_L04_P050" (solid, remove dead copper, pour order 50): 11.3,32 11.3,32.025 11.875,32.6 11.875,58 9.675,60.2 9.675,68.65 9.025,69.3 5.275,69.3 4.875,68.9 4.875,66.2 6,65.075 6,62.25 1.225,57.475 1.225,32.625 1.85,32
5V_VIN on Bottom Layer "5V_VIN_L04_P038" (solid, remove dead copper, pour order 38): 57.675,59.175 57.725,59.175 58.175,59.625 58.175,61.75 58.325,61.9 60.5,61.9 60.875,62.275 60.875,64.175 60.575,64.475 58.475,64.475 56.525,62.525 49.775,62.525 49.525,62.275 49.525,59.75 50.1,59.175
5V_USB_CHGR on Bottom Layer "5V_USB_CHGR_L04_P040" (solid, remove dead copper, pour order 40): 54.392,65.417 56.592,65.417 58.3,67.125 60.65,67.125 60.9,67.375 60.9,69.9 60.475,70.325 50.35,70.325 49.5,69.475 49.5,65 49.7,64.8 53.775,64.8
E5V on Bottom Layer "E5V_L04_P042" (solid, remove dead copper, pour order 42): 49.775,64.525 49.5,64.25 49.5,63.05 49.75,62.8 56.375,62.8 58.325,64.75 60.55,64.75 60.875,65.075 60.875,66.775 60.725,66.925 58.7,66.925 56.825,65.05 54.425,65.05 53.9,64.525
3V3 on Bottom Layer "3V3_L04_P048" (solid, remove dead copper, pour order 48): 34.5,39.325 35.025,38.8 38.3,38.8 38.625,39.125 38.625,63.45 38.3,63.775 36.875,63.775 36.5,63.4 36.5,58.4 34.5,56.4
VDD on Bottom Layer "VDD_L04_P056" (solid, remove dead copper, pour order 56): 29.225,53 28.45,52.225 28.45,50.3 29.723,49.027 29.723,48.123 29.4,47.8 29.4,39.425 33.1,35.725 39.8,35.725 41.45,37.375 41.45,43 41,43.45 39.275,43.45 38.975,43.15 38.975,38.775 38.525,38.325 34.85,38.325 34.1,39.075 34.1,52.45 33.55,53
AGND on Bottom Layer "AGND_L04_P070" (solid, remove dead copper, pour order 70): 36.875,25.95 36.625,25.7 36.625,24.575 37,24.2 40.825,24.2 41.125,23.9 41.125,22.068 42.25,20.943 42.25,9.625 42.875,9 46.15,9 46.55,9.4 46.55,25.425 47.625,26.5 47.625,29.525 45.125,32.025 43.925,32.025 43.7,31.8 43.7,30.9 44.225,30.375 45.05,30.375 46.3,29.125 46.3,27.35 44.9,25.95
VREF on Bottom Layer "VREF_L04_P074" (solid, remove dead copper, pour order 74): 44.375,43.45 44,43.075 44,33.5 47.875,29.625 47.875,25.21 48.21,24.875 50.2,24.875 50.75,25.425 50.75,42.5 49.8,43.45
5V_USB_STLK on Bottom Layer "5V_USB_STLK_L04_P080" (solid, remove dead copper, pour order 80): 58.5,61.4 58.5,59.025 59,58.525 63.225,58.525 63.95,59.25 63.95,73.65 60.2,77.4 49.35,77.4 48.9,76.95 48.9,75.35 49.3,74.95 56.6,74.95 61.125,70.425 61.125,62.05 60.475,61.4
5V_VIN on Bottom Layer "5V_VIN_L04_P014" (solid, remove dead copper, pour order 14): 21.5,47.5 20.375,46.375 20.375,40.47 20.72,40.125 26.575,40.125 26.92,40.47 26.92,47.23 26.65,47.5
VIN on Bottom Layer "VIN_L04_P012" (solid, remove dead copper, pour order 12): 16.975,42.25 16.625,41.9 16.625,37.875 16.875,37.625 19.5,37.625 19.875,38 19.875,41.925 19.55,42.25
GND on Signal Layer 2 "GND_L03_P102" (solid, remove dead copper, pour order 102): 12.15,2.55 12.15,1.7 13.6,0.25 46.5,0.25 48.425,2.175 68.525,2.175 69.825,3.475 69.825,40.95 69.6,41.175 68.375,41.175 68.025,40.825 68.025,13.65 66.975,12.6 47.05,12.6 46.4,11.95 46.4,9.375 45.3,8.275 42.725,8.275 41.35,9.65 41.35,23.775 41,24.125 39.05,24.125 38.675,23.75 38.675,11.375 33.675,6.375 22.25,6.375 18.425,2.55
VREFP on Signal Layer 2 "VREFP_L03_P076" (solid, remove dead copper, pour order 76): 41.225,27.475 40.95,27.2 40.95,25.8 41.25,25.5 45.52,25.5 46,25.02 46,14.425 47.25,13.175 65.925,13.175 66.9,14.15 66.9,39.725 64.21,42.415 64.21,43.965 60.971,47.204 57.704,47.204 57.375,46.875 57.375,36.1 54.125,32.85 54.125,18.7 53.5,18.075 50.45,18.075 50.05,18.475 50.05,23.575 46.875,26.75 44.825,26.75 44.1,27.475
GND on Signal Layer 2 "GND_L03_P094" (solid, remove dead copper, pour order 94): 63.125,66.725 64.075,65.775 64.075,49 62.9,47.825 58.55,47.825 57.85,48.525 57.85,54.1 59.075,55.325 59.075,66.125 59.675,66.725
GND on Signal Layer 2 "GND_L03_P090" (solid, remove dead copper, pour order 90): 37.025,64.45 37.325,64.15 38.525,64.15 39.05,63.625 39.05,58.825 39.425,58.45 39.45,58.475 40.475,58.475 46.95,64.95 46.95,67.175 43.025,71.1 38.6,71.1 37.025,69.525
5V on Signal Layer 2 "5V_L03_P030" (solid, remove dead copper, pour order 30): 58.15,55.775 58.15,68.025 57.62,68.575 57.625,69.25 57.625,69.95 57.325,70.25 53.1,70.25 52.9,70.05 52.925,70.025 52.925,38.125 50.5,35.7 50.5,18.5 53.275,18.5 53.725,18.95 53.725,33.375 56.975,36.625 56.975,54.6
5V_USB_CHGR on Signal Layer 2 "5V_USB_CHGR_L03_P024" (solid, remove dead copper, pour order 24): 43.4,78.525 38.75,73.875 38.75,71.675 39.05,71.375 43.025,71.375 49.6,64.8 51.575,64.8 52.375,65.6 52.375,70.275 52.75,70.65 57.575,70.65 58,70.225 58,67.65 58.275,67.375 63.525,67.375 64.675,66.225 64.675,42.7 65.825,41.55 68.275,41.55 68.875,42.15 68.875,71.45 61.8,78.525
GND on Signal Layer 2 "GND_L03_P096" (solid, remove dead copper, pour order 96): 0.8,24.35 0.7,24.45 0.75,24.5 0.75,41.75 1.125,42.125 13.075,42.125 13.7,41.5 13.7,39.4 14.15,38.95 15.5,38.95 15.775,38.675 15.775,30.25 14.8,29.275 14.8,27.975 11.175,24.35
VIN on Signal Layer 2 "VIN_L03_P018" (solid, remove dead copper, pour order 18): 16.1,29.875 15.25,29.025 15.25,27.55 11.45,23.75 2.625,23.75 2.225,23.35 2.225,18.275 2.625,17.875 18.65,17.875 21.15,20.375 21.15,30.275 21.875,31 21.875,38.375 18.125,42.125 16.385,42.125 16.1,41.84
VBAT on Signal Layer 2 "VBAT_L03_P112" (solid, remove dead copper, pour order 112): 19.725,18.1 18.975,17.35 1.05,17.35 0.9,17.2 0.9,3.6 1.625,2.875 11.75,2.875 12.05,3.175 17.925,3.175 21.625,6.875 25.775,6.875 26.275,7.375 26.275,16.275 25.4,17.15 21.675,17.15 20.725,18.1
E5V on Signal Layer 2 "E5V_L03_P062" (solid, remove dead copper, pour order 62): 4.625,46.65 4.625,44 6.225,42.4 13.025,42.4 15.925,45.3 18.375,45.3 20.925,47.85 36.925,47.85 48.775,59.7 48.775,62.3 49.225,62.75 52.1,62.75 52.25,62.9 52.25,64.375 52.026,64.599 49.599,64.599 49.598,64.6 47.475,64.6 33.125,50.25 8.225,50.25
VDD on Signal Layer 2 "VDD_L03_P058" (solid, remove dead copper, pour order 58): 31.9,50.575 32.475,51.15 32.475,53.95 32.05,54.375 23.3,54.375 17.95,59.725 1.625,59.725 1.225,59.325 1.225,44.025 3.925,44.025 4.25,44.35 4.25,46.775 8.05,50.575
GND on Signal Layer 2 "GND_L03_P088" (solid, remove dead copper, pour order 88): 9.525,82.225 8.075,80.775 8.075,74.55 10.395,72.23 10.395,70.845 9.95,70.4 5.15,70.4 4.125,69.375 4.125,66.375 4.975,65.525 11.825,65.525 14.775,62.575 14.775,60.55 14.45,60.225 0.325,60.225 0.275,60.275 0.275,81.2 1.3,82.225
GND on Signal Layer 2 "GND_L03_P026" (solid, remove dead copper, pour order 26): 56.825,82.35 58.15,81.025 58.15,79.375 58.6,78.925 62,78.925 69.425,71.5 69.9,71.5 69.9,81.45 69,82.35
5V_VIN on Signal Layer 2 "5V_VIN_L03_P016" (solid, remove dead copper, pour order 16): 29.275,40.125 33.425,44.275 47.225,44.275 52.35,49.4 52.35,62.35 52.15,62.55 49.55,62.55 49.375,62.375 49.375,59.525 37.225,47.375 21.4,47.375 18.65,44.625 16.125,44.625 13.975,42.475 13.975,39.45 14.175,39.25 15.475,39.25 15.775,39.55 15.775,41.85 16.3,42.375 18.325,42.375 20.575,40.125
E5V on Signal Layer 2 "E5V_L03_P044" (solid, remove dead copper, pour order 44): 49.6,64.6 49.375,64.375 49.375,62.875 49.5,62.75 52.1,62.75 52.25,62.9 52.25,64.375 52.025,64.6
AGND on Signal Layer 2 "AGND_L03_P068" (solid, remove dead copper, pour order 68): 44,25.25 41.825,23.075 41.825,10.025 43.1,8.75 44.975,8.75 45.775,9.55 45.775,24.75 45.275,25.25
GND on Signal Layer 2 "GND_L03_P092" (solid, remove dead copper, pour order 92): 33.175,54.675 32.825,54.325 32.85,54.3 32.85,51.525 33,51.375 33.725,51.375 35.875,53.525 35.875,54.475 35.675,54.675
3V3 on Signal Layer 2 "3V3_L03_P052" (solid, remove dead copper, pour order 52): 5.325,69.8 4.625,69.1 4.625,66.65 5.2,66.075 12.475,66.075 23.6,54.95 37.125,54.95 38.625,56.45 38.625,63.5 38.3,63.825 36.925,63.825 36.575,63.475 36.575,58.2 35.375,57 26.2,57 13.4,69.8
VREF on Signal Layer 2 "VREF_L03_P072" (solid, remove dead copper, pour order 72): 43.475,43.375 42.975,42.875 42.975,38.425 46.15,35.25 46.15,28 48.075,26.075 49.95,26.075 50.125,26.25 50.125,42.575 49.325,43.375
GND on Signal Layer 2 "GND_L03_P100" (solid, remove dead copper, pour order 100): 52.5,48.65 52.175,48.65 49.725,46.2 49.725,43.675 50.55,42.85 50.55,38.077 50.802,37.825 52.025,37.825 52.65,38.45 52.65,48.5
GND on Signal Layer 2 "GND_L03_P098" (solid, remove dead copper, pour order 98): 22.825,39.85 22.075,39.1 22.075,32.075 22.325,31.825 23.5,31.825 30.45,38.775 30.45,39.5 30.1,39.85
VDD on Signal Layer 2 "VDD_L03_P060" (solid, remove dead copper, pour order 60): 21.173,19.298 21.175,18.4 22,17.575 25.77,17.575 26.775,16.57 26.775,8 28,6.775 28.725,6.775 33.35,6.775 38.15,11.575 38.15,24.865 41.285,28 45.225,28 45.7,28.475 45.7,34.95 42.375,38.275 42.375,42.925 41.9,43.425 33.675,43.425 31.35,41.1 31.35,39.25 22.025,29.925 22.025,20.15
3V3_STLK on Signal Layer 2 "3V3_STLK_L03_P020" (solid, remove dead copper, pour order 20): 10.4,81.4 9.725,81.4 8.625,80.3 8.625,75.15 26.35,57.425 35.375,57.425 36.35,58.4 36.35,65.925 36.65,66.225 36.65,69.475 38.4,71.225 38.4,73.925 43.45,78.975 57.35,78.975 57.7,79.325 57.7,80.75 57.2,81.25 39.95,81.25 37.125,78.425 37.125,72.65 36.025,71.55 35.2,71.55 34.025,72.725 33.425,72.725 33.025,73.125 33.025,74.925 30.675,77.275 30.675,80.75 30.05,81.375
GND on Signal Layer 2 "GND_L03_P022" (solid, remove dead copper, pour order 22): 30.925,82.475 30.925,77.425 33.25,75.1 33.25,73.35 33.6,73 34.1,73 35.475,71.625 35.725,71.625 36.9,72.8 36.9,77.425 37.801,78.326 37.801,82.474 37.8,82.475
GND on Signal Layer 1 "GND_L02_P000" (solid, remove dead copper, pour order 0): 0.325,82.5 0,82.175 0,2.4 0.4,2 11.5,2 13.5,0 46.5,0 48.5,2 69.875,2 70,2.125 70,81.975 69.475,82.5

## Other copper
Top Layer:
  pour cut-out: 8.8,70.275 8.875,70.35 11.85,70.35 12.55,69.65 13.913,69.65 14.022,69.541 14.022,69.065 14.265,69.065 14.275,69.075 16.5,69.075 17.85,67.725 17.85,64.7 17.784,64.7 17.518,64.434 17.502,64.45 14.5,64.45 14.126,64.076 14.126,62.336 13.465,61.675 6.975,61.675 6.75,61.9 6.75,70.05 7,70.3
  pour cut-out: 22.216,70.344 22.216,61.884 23.184,60.916 27.609,60.916 27.65,60.957 27.65,62.45 24.5,62.45 23.525,63.425 23.55,63.45 23.55,73.5 24.75,74.7 31.825,74.7 32.116,74.991 32.116,75.884 30.376,75.884 30.36,75.9 25.275,75.9 24.35,74.975 21.446,74.975 20.725,74.254 20.725,71.25 21.625,70.35 21.725,70.35
  pour cut-out: 31.054,60.916 35.959,60.916 37.184,62.141 37.184,69.674 37.108,69.75 35.95,69.75 35.95,63.025 35.05,62.125 31.025,62.125
  text "1" at 34.37,2.04 h2.5
Signal Layer 1:
  text "2" at 36.12,2.04 h2.5
Signal Layer 2:
  text "3" at 39.12,2.04 h2.5
Bottom Layer:
  pour cut-out: 25.069,19.031 25.069,16.519 25.05,16.5 25.052,16.498 39.795,16.498 39.695,16.598 39.695,18.965
  pour cut-out: 33.37,20.34 36.341,20.34 36.3,20.381 36.3,24.91 35.72,25.49 33.37,25.49
  text "4" at 41.12,2.04 h2.5
Multi-Layer:
  pour cut-out: 33.62,4.29 33.62,1.29 42.12,1.29 42.12,4.29

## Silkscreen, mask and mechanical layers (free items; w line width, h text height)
Top Overlay:
  drawing of 813 lines, arcs and shapes, not listed
  text "USB" at 40.075,79.125 h1.7
  text "STLK" at 40.125,77.7 h1.7
  text "OC" at 46.15,76.95 h1.7
  text "STLK" at 18.25,76.9 h1.5
  text "COM" at 61.875,76.775 h1.7 r90
  text "RESERVED" at 7.35,75.9 h1.5
  text "_RST" at 18.25,75.575 h1.5
  text "GND" at 65.175,73.425 h1.7
  text "GND" at 1.625,73.375 h1.7
  text "5V_PWR" at 63.925,70.5 h1.5
  text "5V_CHRG" at 61.625,68.075 h1.7
  text "E5V" at 61.625,65.4 h1.7
  text "5V_VIN" at 61.625,62.95 h1.7
  text "5V_STLK" at 61.625,60.425 h1.7
  text "5V_SEL" at 55.125,58.15 h1.7
  text "DEBUG" at 7.425,58.05 h2
  text "SCL/D15" at 51.625,49.25 h1.7
  text "RESET" at 40.425,48.55 h2
  text "USER" at 24.575,48.525 h2
  text "RST" at 12.55,48.1 h1.7
  text "SDA/D14" at 51.525,46.625 h1.7
  text "E5V" at 7.47,45.115 h1.7
  text "VREFP" at 52.65,44.1 h1.7
  text "VREF" at 40,42.95 h2
  text "GND" at 7.314,42.632 h1.7
  text "GND" at 54.475,41.525 h1.7
  text "IDD" at 28.625,40.55 h2
  text "SCK/D13" at 51.475,39 h1.7
  text "3V3" at 12.394,37.552 h1.7
  text "MISO/D12" at 50.775,36.55 h1.7
  text "www.st.com/stm32nucleo" at 18.625,35.075 h2
  text "NRST" at 12.394,34.758 h1.7
  text "PWM/MOSI/D11" at 46.8,33.975 h1.7
  text "3V3" at 12.394,32.472 h1.7
  text "PWM/CS/D10" at 48.425,31.475 h1.7
  text "5V" at 12.394,29.678 h1.7
  text "PWM/D9" at 51.75,28.875 h1.7
  text "GND" at 12.25,27.275 h1.7
  text "D8" at 55.875,26.3 h1.7
  text "POWER" at 16.775,25.875 h1.7 r90
  text "GND" at 12.394,24.598 h1.7
  text "D7" at 55.9,22.325 h1.7
  text "VIN" at 12.394,22.058 h1.7
  text "PWM/D6" at 52.15,19.725 h1.6
  text "BOOT0" at 15.4,18.8 h2
  text "PWM/D5" at 51.775,17.2 h1.7
  text "A0" at 12.394,16.978 h1.7
  text "24MHz" at 32.775,15.05 h0.8
  text "32.768KHz" at 26.4,14.775 h0.8
  text "D4" at 55.9,14.675 h1.7
  text "A1" at 12.394,14.438 h1.7
  text "PWM/D3" at 51.8,12.075 h1.7
  text "A2" at 12.394,11.898 h1.7
  text "CPN" at 38.875,10.225 h1.5
  text "AIN" at 15.55,10.025 h1.7 r90
  text "D2" at 55.875,9.575 h1.7
  text "A3" at 12.394,9.358 h1.7
  text "TX/D1" at 53.675,7.025 h1.7
  text "A4" at 12.394,6.818 h1.7
  text "RX/D0" at 53.375,4.425 h1.7
  text "A5" at 12.394,4.278 h1.7
  text "MB1367C" at 21.675,1.525 h2.5
Bottom Overlay:
  drawing of 365 lines, arcs and shapes, not listed
  text "CN12" at 5.8,80.45 h2
  text "CN11" at 68.7,80.375 h2
  text "CN1" at 42.575,79.575 h2
  text "1" at 9.575,79.417 h2
  text "1" at 29.425,79.417 h2
  text "CN2" at 16.85,77.1 h2
  text "JP1" at 27.225,77.1 h2
  text "1" at 36.6,76.367 h2
  text "1" at 65.075,75.492 h2
  text "1" at 5.525,75.417 h2
  text "CN4" at 12.1,72.575 h2
  text "SN" at 34.75,72.5 h1.5
  text "JP5" at 59.35,70.125 h2
  text "2" at 14.25,69.192 h2
  text "1" at 7.425,69.125 h2
  text "RoHS" at 37.095,62.24 h1.6
  text "13" at 7.4,61.55 h2
  text "14" at 15.05,61.55 h2
  text "COMPLIANT" at 37.495,60.84 h0.8
  text "1" at 61.25,60.267 h2
  text "2002/95/EC" at 37.995,59.54 h0.8
  text "CN7" at 6.25,52.375 h2
  text "CN10" at 67.675,52.3 h2
  text "1" at 1.98,50.252 h2
  text "2" at 68.93,50.127 h2
  text "1" at 9.35,50.092 h2
  text "10" at 62.201,49.059 h2
  text "3" at 1.98,47.712 h2
  text "4" at 68.93,47.587 h2
  text "9" at 61.312,46.519 h2
  text "JP3" at 12.5,45.275 h2
  text "5" at 1.98,45.172 h2
  text "6" at 68.93,45.047 h2
  text "8" at 61.312,43.979 h2
  text "JP8" at 43.85,42.9 h2
  text "JP6" at 35.775,42.85 h2
  text "7" at 1.98,42.632 h2
  text "8" at 68.93,42.507 h2
  text "CN6" at 12.675,42.35 h2
  text "7" at 61.312,41.439 h2
  text "1" at 47.175,40.542 h2
  text "9" at 1.98,40.092 h2
  text "1" at 9.6,40.092 h2
  text "10" at 69.692,39.967 h2
  text "1" at 35.042,39.075 h2 r270
  text "6" at 61.312,38.899 h2
  text "11" at 1.98,37.552 h2
  text "2" at 9.6,37.552 h2
  text "12" at 69.692,37.427 h2
  text "5" at 61.312,36.359 h2
  text "13" at 1.98,35.012 h2
  text "3" at 9.6,35.012 h2
  text "14" at 69.692,34.887 h2
  text "CN5" at 56.4,34.15 h2 r270
  text "4" at 61.312,33.819 h2
  text "15" at 1.98,32.472 h2
  text "4" at 9.6,32.472 h2
  text "16" at 69.692,32.347 h2
  text "3" at 61.312,31.279 h2
  text "17" at 1.98,29.932 h2
  text "5" at 9.6,29.932 h2
  text "18" at 69.692,29.807 h2
  text "2" at 61.312,28.739 h2
  text "19" at 1.98,27.392 h2
  text "6" at 9.6,27.392 h2
  text "20" at 69.819,27.267 h2
  text "1" at 60.931,26.199 h2
  text "JP7" at 19.75,26.025 h2
  text "21" at 1.98,24.852 h2
  text "7" at 9.6,24.852 h2
  text "22" at 69.819,24.727 h2
  text "23" at 1.98,22.312 h2
  text "8" at 9.6,22.312 h2
  text "24" at 69.819,22.187 h2
  text "8" at 61.312,22.135 h2
  text "1" at 20.425,21.142 h2
  text "25" at 1.98,19.772 h2
  text "26" at 69.819,19.647 h2
  text "7" at 61.312,19.595 h2
  text "CN8" at 12.525,19.525 h2
  text "27" at 1.98,17.232 h2
  text "1" at 9.6,17.232 h2
  text "28" at 69.819,17.107 h2
  text "6" at 61.312,17.055 h2
  text "29" at 1.98,14.692 h2
  text "2" at 9.6,14.692 h2
  text "30" at 69.819,14.567 h2
  text "5" at 61.312,14.515 h2
  text "31" at 1.98,12.152 h2
  text "3" at 9.6,12.152 h2
  text "32" at 69.819,12.027 h2
  text "4" at 61.312,11.975 h2
  text "CN9" at 56.25,11.675 h2 r270
  text "33" at 1.98,9.612 h2
  text "4" at 9.6,9.612 h2
  text "34" at 69.819,9.487 h2
  text "3" at 61.312,9.435 h2
  text "35" at 1.98,7.072 h2
  text "5" at 9.6,7.072 h2
  text "36" at 69.819,6.947 h2
  text "2" at 61.312,6.895 h2
  text "37" at 1.98,4.532 h2
  text "6" at 9.6,4.532 h2
  text "38" at 69.819,4.407 h2
  text "1" at 60.931,4.355 h2
Top Solder:
  rectangle: 33.87,1.54 41.87,4.04
Bottom Solder:
  rectangle: 33.87,1.54 41.87,4.04
M1-Board Shape:
  lines w0.1: 48.5,2 68,2 ccw(c68,4) 70,4 70,58 70,80.5 ; 48.5,2 48.5,2 ; 48.5,2 46.5,0 13.5,0 11.5,2 2,2 cw(c2,4) 0,4 0,58 0,80.5 cw(c2,80.5) 2,82.5 68,82.5 cw(c68,80.5) 70,80.5 ; 70,80.5 70,80.5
